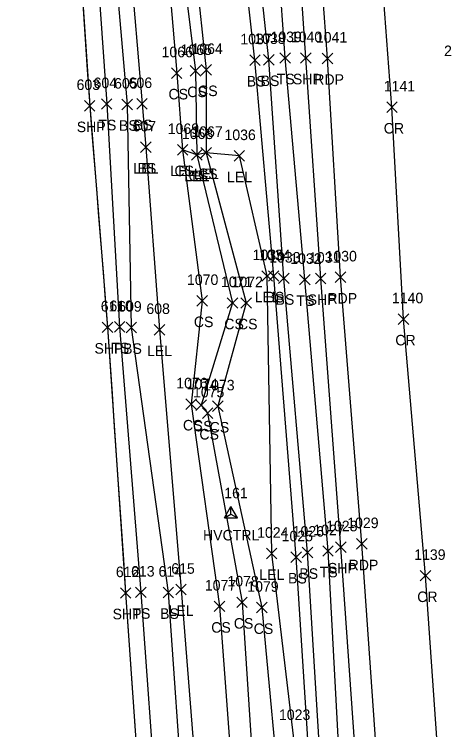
# Model space of a CAD drawing. Extents: x 1650221 to 1650634, y 244606 to 249996.
# Drawn here: x 1650303 to 1650384.9, y 245976.3 to 246112 of the extents above; entities that cross this region are included whole.
import ezdxf

# ---------------------------------------------------------------- set-up
doc = ezdxf.new("R2010")
doc.units = 0
for name, color, linetype in [('C_A', 7, 'Continuous'), ('C_I', 7, 'Continuous'), ('CPSM', 7, 'Continuous'), ('L_A', 7, 'Continuous'), ('L_I', 7, 'Continuous'), ('L_TIC', 7, 'Continuous'), ('LARO', 7, 'Continuous'), ('LELB', 7, 'Continuous'), ('LSOGP', 7, 'Continuous'), ('P_A', 7, 'Continuous'), ('P_I', 7, 'Continuous'), ('P_TIC', 7, 'Continuous'), ('PET', 7, 'Continuous'), ('PRC', 7, 'Continuous'), ('PSP', 7, 'Continuous')]:
    doc.layers.add(name, color=color, linetype=linetype)

msp = doc.modelspace()

# ---------------------------------------------------------------- linework, layer by layer
at = {"layer": 'CPSM'}
for p, q in [((1650342.85, 246016.46), (1650344.1, 246018.62)), ((1650345.35, 246016.46), (1650344.1, 246018.62)), ((1650344.1, 246017.18), (1650344.1, 246018.62)), ((1650342.85, 246016.46), (1650344.1, 246017.18)), ((1650342.85, 246016.46), (1650345.35, 246016.46)), ((1650344.1, 246017.18), (1650344.1, 246017.18)), ((1650344.1, 246017.18), (1650345.35, 246016.46))]:
    msp.add_line(p, q, dxfattribs=at)
at = {"layer": 'L_TIC'}
for points in [[(1650353.38, 246102.74), (1650355.38, 246104.74)], [(1650355.38, 246102.74), (1650353.38, 246104.74)], [(1650347.65, 246102.32), (1650349.65, 246104.32)], [(1650349.65, 246102.32), (1650347.65, 246104.32)], [(1650350.29, 246102.4), (1650352.29, 246104.4)], [(1650352.29, 246102.4), (1650350.29, 246104.4)], [(1650332.79, 246099.87), (1650334.79, 246101.87)], [(1650334.79, 246099.87), (1650332.79, 246101.87)], [(1650336.35, 246100.3), (1650338.35, 246102.3)], [(1650338.35, 246100.3), (1650336.35, 246102.3)], [(1650338.41, 246100.5), (1650340.41, 246102.5)], [(1650340.41, 246100.5), (1650338.41, 246102.5)], [(1650319.5, 246094.01), (1650321.5, 246096.01)], [(1650321.5, 246094.01), (1650319.5, 246096.01)], [(1650323.39, 246093.92), (1650325.39, 246095.92)], [(1650325.39, 246093.92), (1650323.39, 246095.92)], [(1650326.21, 246094.03), (1650328.21, 246096.03)], [(1650328.21, 246094.03), (1650326.21, 246096.03)], [(1650326.92, 246085.8), (1650328.92, 246087.8)], [(1650328.92, 246085.8), (1650326.92, 246087.8)], [(1650326.92, 246085.8), (1650328.92, 246087.8)], [(1650328.92, 246085.8), (1650326.92, 246087.8)], [(1650333.92, 246085.31), (1650335.92, 246087.31)], [(1650335.92, 246085.31), (1650333.92, 246087.31)], [(1650333.92, 246085.31), (1650335.92, 246087.31)], [(1650335.92, 246085.31), (1650333.92, 246087.31)], [(1650336.6, 246084.35), (1650338.6, 246086.35)], [(1650338.6, 246084.35), (1650336.6, 246086.35)], [(1650336.6, 246084.35), (1650338.6, 246086.35)], [(1650338.6, 246084.35), (1650336.6, 246086.35)], [(1650338.4, 246084.76), (1650340.4, 246086.76)], [(1650340.4, 246084.76), (1650338.4, 246086.76)], [(1650338.4, 246084.76), (1650340.4, 246086.76)], [(1650340.4, 246084.76), (1650338.4, 246086.76)], [(1650344.69, 246084.15), (1650346.69, 246086.15)], [(1650346.69, 246084.15), (1650344.69, 246086.15)], [(1650349.97, 246061.37), (1650351.97, 246063.37)], [(1650351.97, 246061.37), (1650349.97, 246063.37)], [(1650351.21, 246061.35), (1650353.21, 246063.35)], [(1650353.21, 246061.35), (1650351.21, 246063.35)], [(1650353.12, 246060.91), (1650355.12, 246062.91)], [(1650355.12, 246060.91), (1650353.12, 246062.91)], [(1650357.12, 246060.67), (1650359.12, 246062.67)], [(1650359.12, 246060.67), (1650357.12, 246062.67)], [(1650337.61, 246056.66), (1650339.61, 246058.66)], [(1650339.61, 246056.66), (1650337.61, 246058.66)], [(1650343.39, 246056.25), (1650345.39, 246058.25)], [(1650345.39, 246056.25), (1650343.39, 246058.25)], [(1650345.97, 246056.24), (1650347.97, 246058.24)], [(1650347.97, 246056.24), (1650345.97, 246058.24)], [(1650321.95, 246051.7), (1650323.95, 246053.7)], [(1650323.95, 246051.7), (1650321.95, 246053.7)], [(1650324.17, 246051.59), (1650326.17, 246053.59)], [(1650326.17, 246051.59), (1650324.17, 246053.59)], [(1650329.53, 246051.16), (1650331.53, 246053.16)], [(1650331.53, 246051.16), (1650329.53, 246053.16)], [(1650335.54, 246037.05), (1650337.54, 246039.05)], [(1650337.54, 246037.05), (1650335.54, 246039.05)], [(1650337.44, 246036.87), (1650339.44, 246038.87)], [(1650339.44, 246036.87), (1650337.44, 246038.87)], [(1650340.6, 246036.66), (1650342.6, 246038.66)], [(1650342.6, 246036.66), (1650340.6, 246038.66)], [(1650338.66, 246035.33), (1650340.66, 246037.33)], [(1650340.66, 246035.33), (1650338.66, 246037.33)], [(1650357.64, 246008.9), (1650359.64, 246010.9)], [(1650359.64, 246008.9), (1650357.64, 246010.9)], [(1650361.52, 246009.18), (1650363.52, 246011.18)], [(1650363.52, 246009.18), (1650361.52, 246011.18)], [(1650350.83, 246008.69), (1650352.83, 246010.69)], [(1650352.83, 246008.69), (1650350.83, 246010.69)], [(1650355.49, 246008.02), (1650357.49, 246010.02)], [(1650357.49, 246008.02), (1650355.49, 246010.02)], [(1650325.97, 246001.33), (1650327.97, 246003.33)], [(1650327.97, 246001.33), (1650325.97, 246003.33)], [(1650331.19, 246001.3), (1650333.19, 246003.3)], [(1650333.19, 246001.3), (1650331.19, 246003.3)], [(1650333.61, 246001.86), (1650335.61, 246003.86)], [(1650335.61, 246001.86), (1650333.61, 246003.86)], [(1650345.19, 245999.45), (1650347.19, 246001.45)], [(1650347.19, 245999.45), (1650345.19, 246001.45)], [(1650340.91, 245998.68), (1650342.91, 246000.68)], [(1650342.91, 245998.68), (1650340.91, 246000.68)], [(1650348.97, 245998.44), (1650350.97, 246000.44)], [(1650350.97, 245998.44), (1650348.97, 246000.44)]]:
    msp.add_lwpolyline(points, dxfattribs=at)
at = {"layer": 'LARO'}
for points in [[(1650327.92, 246086.8), (1650330.53, 246052.16), (1650334.61, 246002.86), (1650338.05, 245959.72), (1650343.88, 245907.71), (1650343, 245877.3), (1650345.46, 245825.54), (1650349.71, 245779.85), (1650351.41, 245747.87)], [(1650358.12, 245745.13), (1650361.51, 245744.75), (1650366.42, 245745.74), (1650368.11, 245782.09), (1650367.43, 245837.26), (1650363.68, 245883.96), (1650357.84, 245936.08), (1650355.98, 245975.11), (1650351.83, 246009.69), (1650350.97, 246062.37), (1650345.69, 246085.15), (1650339.4, 246085.76), (1650337.6, 246085.35), (1650334.92, 246086.31)]]:
    msp.add_lwpolyline(points, dxfattribs=at)
at = {"layer": 'LELB'}
for points in [[(1650306.13, 246294.16), (1650309.79, 246242.03), (1650313.68, 246189.71), (1650316.64, 246149.59), (1650320.5, 246095.01), (1650322.95, 246052.7), (1650326.97, 246002.33), (1650330.11, 245959.39), (1650334.35, 245907.17), (1650335.99, 245876.74), (1650339.33, 245825.96), (1650342.38, 245779.38), (1650345.15, 245747.14), (1650349.13, 245703.09), (1650351.39, 245660.59)], [(1650313.05, 246293.73), (1650316.43, 246243), (1650319.8, 246189.11), (1650319.58, 246150.09), (1650324.39, 246094.92), (1650325.17, 246052.59), (1650332.19, 246002.3), (1650335.15, 245959.83), (1650340.06, 245907.3), (1650338.79, 245876.74), (1650342.62, 245825.69), (1650346.47, 245779.47), (1650348.22, 245747.63), (1650355.71, 245703.22), (1650358.45, 245660.47)], [(1650388.27, 245633.5), (1650384.04, 245685.26), (1650381.95, 245734.17), (1650378.46, 245783.41), (1650374.43, 245837.02), (1650371.37, 245883.98), (1650366.52, 245935.98), (1650362.52, 246010.18), (1650358.12, 246061.67), (1650354.38, 246103.74), (1650350.77, 246155.06), (1650347.92, 246191.34), (1650347.02, 246221.82), (1650344.37, 246259.89)], [(1650380.77, 245632.36), (1650373.15, 245685.41), (1650374.88, 245733.26), (1650375.49, 245783.17), (1650371.23, 245836.92), (1650367.57, 245883.9), (1650363.2, 245935.62), (1650358.64, 246009.9), (1650354.12, 246061.91), (1650351.29, 246103.4), (1650345.69, 246155.39), (1650338.49, 246190.86), (1650334.26, 246221.72), (1650338.38, 246258.83)], [(1650328.67, 246191.15), (1650321.64, 246178.6), (1650322.52, 246149.98), (1650327.21, 246095.03), (1650327.92, 246086.8)], [(1650363.45, 245718.21), (1650371.15, 245733.08), (1650372.9, 245782.86), (1650369.48, 245836.8), (1650365.6, 245884.56), (1650361.18, 245936.01), (1650356.49, 246009.02), (1650352.21, 246062.35), (1650348.65, 246103.32), (1650342.84, 246155.21), (1650338.6, 246177.03), (1650330.57, 246190.17)], [(1650328.84, 246183.64), (1650328.53, 246172.08), (1650332.8, 246138.35), (1650337.35, 246101.3), (1650337.6, 246085.35), (1650344.39, 246057.25), (1650338.44, 246037.87), (1650339.66, 246036.33), (1650346.19, 246000.45), (1650348.93, 245958.63)], [(1650328.84, 246183.64), (1650330.78, 246172.34), (1650335.45, 246138.48), (1650339.41, 246101.5), (1650339.4, 246085.76), (1650346.97, 246057.24), (1650341.6, 246037.66), (1650349.97, 245999.44), (1650353.79, 245958.12), (1650353.48, 245944.94), (1650356.23, 245920.49), (1650358.19, 245889.9), (1650358.98, 245871.02), (1650360.94, 245846.57), (1650361.06, 245820.39), (1650362.02, 245813.72), (1650361.66, 245801.18), (1650362.26, 245786.97), (1650360.46, 245769.54), (1650362.23, 245766.97), (1650362.34, 245763.52), (1650361.09, 245756.75)], [(1650325.43, 246172.96), (1650330.68, 246138.03), (1650333.79, 246100.87), (1650334.92, 246086.31), (1650338.61, 246057.66), (1650336.54, 246038.05), (1650341.91, 245999.68), (1650344.98, 245958.76)]]:
    msp.add_lwpolyline(points, dxfattribs=at)
at = {"layer": 'LSOGP'}
msp.add_lwpolyline([(1650315.92, 246115.05), (1650316.37, 246108.25), (1650316.82, 246101.46), (1650317.27, 246094.66), (1650317.69, 246089.41), (1650318.12, 246084.15), (1650318.54, 246078.9), (1650318.96, 246073.65), (1650319.38, 246068.39), (1650319.8, 246063.14), (1650320.23, 246057.88), (1650320.65, 246052.63), (1650321.08, 246046.33), (1650321.51, 246040.03), (1650321.94, 246033.73), (1650322.37, 246027.42), (1650322.8, 246021.12), (1650323.23, 246014.82), (1650323.66, 246008.52), (1650324.09, 246002.22), (1650324.46, 245996.81), (1650324.84, 245991.41), (1650325.22, 245986.01), (1650325.6, 245980.6), (1650325.98, 245975.2)], dxfattribs=at)
at = {"layer": 'P_TIC'}
for points in [[(1650357.32, 246102.73), (1650359.32, 246104.73)], [(1650359.32, 246102.73), (1650357.32, 246104.73)], [(1650361.42, 246102.65), (1650363.42, 246104.65)], [(1650363.42, 246102.65), (1650361.42, 246104.65)], [(1650316.27, 246093.66), (1650318.27, 246095.66)], [(1650318.27, 246093.66), (1650316.27, 246095.66)], [(1650373.67, 246093.39), (1650375.67, 246095.39)], [(1650375.67, 246093.39), (1650373.67, 246095.39)], [(1650360.13, 246060.87), (1650362.13, 246062.87)], [(1650362.13, 246060.87), (1650360.13, 246062.87)], [(1650363.91, 246061.13), (1650365.91, 246063.13)], [(1650365.91, 246061.13), (1650363.91, 246063.13)], [(1650375.87, 246053.19), (1650377.87, 246055.19)], [(1650377.87, 246053.19), (1650375.87, 246055.19)], [(1650319.65, 246051.63), (1650321.65, 246053.63)], [(1650321.65, 246051.63), (1650319.65, 246053.63)], [(1650367.95, 246010.52), (1650369.95, 246012.52)], [(1650369.95, 246010.52), (1650367.95, 246012.52)], [(1650363.94, 246009.92), (1650365.94, 246011.92)], [(1650365.94, 246009.92), (1650363.94, 246011.92)], [(1650380.02, 246004.49), (1650382.02, 246006.49)], [(1650382.02, 246004.49), (1650380.02, 246006.49)], [(1650323.09, 246001.22), (1650325.09, 246003.22)], [(1650325.09, 246001.22), (1650323.09, 246003.22)]]:
    msp.add_lwpolyline(points, dxfattribs=at)
at = {"layer": 'PET'}
msp.add_lwpolyline([(1650395.97, 245634.45), (1650392.36, 245685.55), (1650388.92, 245734.97), (1650385.44, 245783.96), (1650381.32, 245836.98), (1650377.76, 245885.16), (1650374.23, 245935.73), (1650368.95, 246011.52), (1650364.91, 246062.13), (1650362.42, 246103.65), (1650358.62, 246155.34), (1650355.82, 246192.67), (1650353.63, 246221.52), (1650350.67, 246260.72)], dxfattribs=at)
at = {"layer": 'PRC'}
msp.add_lwpolyline([(1650407.05, 245649.82), (1650403.01, 245697.04), (1650399.62, 245752.27), (1650396.14, 245798.38), (1650392.81, 245844.54), (1650388.72, 245894.05), (1650384.12, 245961.1), (1650381.02, 246005.49), (1650376.87, 246054.19), (1650374.67, 246094.39), (1650371.04, 246142.56), (1650368.19, 246182.74), (1650365.1, 246222.23), (1650362.04, 246265.67)], dxfattribs=at)
at = {"layer": 'PSP'}
for points in [[(1650302.95, 246294.11), (1650306.82, 246242.11), (1650310.69, 246189.86), (1650313.65, 246149.04), (1650317.27, 246094.66), (1650320.65, 246052.63), (1650324.09, 246002.22), (1650327.12, 245958.99), (1650330.71, 245907.14), (1650333.14, 245876.4), (1650336.6, 245825.63), (1650340.18, 245778.77), (1650342.47, 245746.4), (1650345.78, 245703.18), (1650348.63, 245659.65)], [(1650392.23, 245633.8), (1650388.44, 245685.1), (1650385.12, 245734.49), (1650381.93, 245783.82), (1650377.54, 245837.05), (1650373.94, 245884.64), (1650370.21, 245936.33), (1650364.94, 246010.92), (1650361.13, 246061.87), (1650358.32, 246103.73), (1650354.8, 246155.14), (1650352.16, 246192.13), (1650349.68, 246222.04), (1650346.67, 246260.34)]]:
    msp.add_lwpolyline(points, dxfattribs=at)

# ---------------------------------------------------------------- texts
at = {"layer": 'C_A'}
msp.add_text('HVCTRL', height=2, dxfattribs=at).set_placement((1650338.79, 246012.18))
at = {"layer": 'C_I'}
msp.add_text('161', height=2, dxfattribs=at).set_placement((1650342.82, 246020.18))
at = {"layer": 'L_A'}
for s, p in [('BS', (1650349.73, 246098.4)), ('TS', (1650352.79, 246098.74)), ('BS', (1650347.09, 246098.32)), ('CS', (1650332.23, 246095.87)), ('CS', (1650335.79, 246096.3)), ('CS', (1650337.85, 246096.5)), ('TS', (1650318.91, 246090.01)), ('BS', (1650322.83, 246089.92)), ('BS', (1650325.65, 246090.03)), ('LEL', (1650325.55, 246081.8)), ('BS', (1650326.36, 246081.8)), ('LEL', (1650332.56, 246081.31)), ('CS', (1650333.36, 246081.31)), ('LEL', (1650337.03, 246080.76)), ('CS', (1650337.84, 246080.76)), ('LEL', (1650335.24, 246080.35)), ('CS', (1650336.04, 246080.35)), ('LEL', (1650343.33, 246080.15)), ('LEL', (1650348.61, 246057.37)), ('BS', (1650350.65, 246057.35)), ('BS', (1650352.56, 246056.91)), ('TS', (1650356.53, 246056.67)), ('CS', (1650337.05, 246052.66)), ('CS', (1650342.83, 246052.25)), ('CS', (1650345.42, 246052.24)), ('TS', (1650321.36, 246047.7)), ('BS', (1650323.61, 246047.59)), ('LEL', (1650328.17, 246047.16)), ('CS', (1650334.98, 246033.05)), ('CS', (1650336.89, 246032.87)), ('CS', (1650340.05, 246032.66)), ('CS', (1650338.1, 246031.33)), ('LEL', (1650349.47, 246004.69)), ('BS', (1650357.08, 246004.9)), ('TS', (1650360.93, 246005.18)), ('BS', (1650354.93, 246004.02)), ('TS', (1650325.38, 245997.33)), ('BS', (1650330.63, 245997.3)), ('LEL', (1650332.24, 245997.86)), ('CS', (1650344.63, 245995.45)), ('CS', (1650340.35, 245994.68)), ('CS', (1650348.41, 245994.44))]:
    msp.add_text(s, height=2, dxfattribs=at).set_placement(p)
at = {"layer": 'L_I'}
for s, p in [('1039', (1650351.6, 246106.74)), ('1037', (1650345.88, 246106.32)), ('1038', (1650348.52, 246106.4)), ('1066', (1650330.92, 246103.87)), ('1065', (1650334.53, 246104.3)), ('1064', (1650336.59, 246104.5)), ('604', (1650318.01, 246098.01)), ('605', (1650321.9, 246097.92)), ('606', (1650324.67, 246098.03)), ('607', (1650325.43, 246089.8)), ('607', (1650325.43, 246089.8)), ('1069', (1650332.09, 246089.31)), ('1069', (1650332.09, 246089.31)), ('1068', (1650334.78, 246088.35)), ('1068', (1650334.78, 246088.35)), ('1067', (1650336.58, 246088.76)), ('1067', (1650336.58, 246088.76)), ('1036', (1650342.86, 246088.15)), ('1035', (1650348.2, 246065.37)), ('1034', (1650349.44, 246065.35)), ('1033', (1650351.35, 246064.91)), ('1032', (1650355.35, 246064.67)), ('1070', (1650335.75, 246060.66)), ('1071', (1650342.19, 246060.25)), ('1072', (1650344.2, 246060.24)), ('610', (1650321.02, 246055.7)), ('609', (1650322.68, 246055.59)), ('608', (1650328.04, 246055.16)), ('1076', (1650333.71, 246041.05)), ('1074', (1650335.67, 246040.87)), ('1073', (1650338.83, 246040.66)), ('1075', (1650336.89, 246039.33)), ('1026', (1650355.81, 246012.9)), ('1027', (1650359.74, 246013.18)), ('1024', (1650349.06, 246012.69)), ('1025', (1650353.72, 246012.02)), ('613', (1650325.13, 246005.33)), ('614', (1650330.34, 246005.3)), ('615', (1650332.76, 246005.86)), ('1078', (1650343.42, 246003.45)), ('1077', (1650339.13, 246002.68)), ('1079', (1650347.19, 246002.44)), ('1023', (1650353.21, 245978.11))]:
    msp.add_text(s, height=2, dxfattribs=at).set_placement(p)
at = {"layer": 'P_A'}
for s, p in [('SHP', (1650355.85, 246098.73)), ('RDP', (1650359.91, 246098.65)), ('SHP', (1650314.81, 246089.66)), ('CR', (1650373.1, 246089.39)), ('SHP', (1650358.66, 246056.87)), ('RDP', (1650362.4, 246057.13)), ('CR', (1650375.3, 246049.19)), ('SHP', (1650318.18, 246047.63)), ('RDP', (1650366.43, 246006.52)), ('SHP', (1650362.48, 246005.92)), ('CR', (1650379.46, 246000.49)), ('SHP', (1650321.62, 245997.22))]:
    msp.add_text(s, height=2, dxfattribs=at).set_placement(p)
at = {"layer": 'P_I'}
for s, p in [('1040', (1650355.46, 246106.73)), ('1041', (1650360.22, 246106.65)), ('2140', (1650384.56, 246104.09)), ('603', (1650314.78, 246097.66)), ('1141', (1650373.11, 246097.39)), ('1031', (1650358.92, 246064.87)), ('1030', (1650362.05, 246065.13)), ('1140', (1650374.66, 246057.19)), ('611', (1650319.37, 246055.63)), ('1029', (1650366.17, 246014.52)), ('1028', (1650362.17, 246013.92)), ('1139', (1650378.89, 246008.49)), ('612', (1650322.24, 246005.22))]:
    msp.add_text(s, height=2, dxfattribs=at).set_placement(p)

doc.saveas('drawing.dxf')
